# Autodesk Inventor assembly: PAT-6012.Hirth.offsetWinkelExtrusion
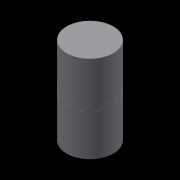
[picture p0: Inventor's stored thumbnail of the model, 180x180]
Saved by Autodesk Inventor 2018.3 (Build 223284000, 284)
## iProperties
Created: 2020-03
Part Number: PAT-6012.Hirth.offsetWinkelExtrusion
Document SubType Name: Assembly
Designer: Th. Mörgeli
Mass: 35.2883 g
Surface Area: 96.7252 cm^2
Volume: 35.2883 cm^3
Density: 1 g/cm^3
Author: Th. Mörgeli
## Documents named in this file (2)
- C:\Users\mothomas\Documents\Inventor\Patterson\PATHirth.offsetWinkelExtrusion.iam
- C:\Users\mothomas\Documents\Inventor\Patterson\PATHirth.offsetWinkelExtrusion.ipt
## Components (2 placed, 1 different names)
1. PATHirth.offsetWinkelExtrusion:1 — Mate:1, Mate:2, Angle:1
2. PATHirth.offsetWinkelExtrusion:2 — Mate:1, Mate:2, Angle:1
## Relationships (3: Mate 2, Angle 1)
- Mate:1: PATHirth.offsetWinkelExtrusion:1 ↔ PATHirth.offsetWinkelExtrusion:2
- Mate:2: PATHirth.offsetWinkelExtrusion:1 ↔ PATHirth.offsetWinkelExtrusion:2
- Angle:1: PATHirth.offsetWinkelExtrusion:1 ↔ PATHirth.offsetWinkelExtrusion:2
